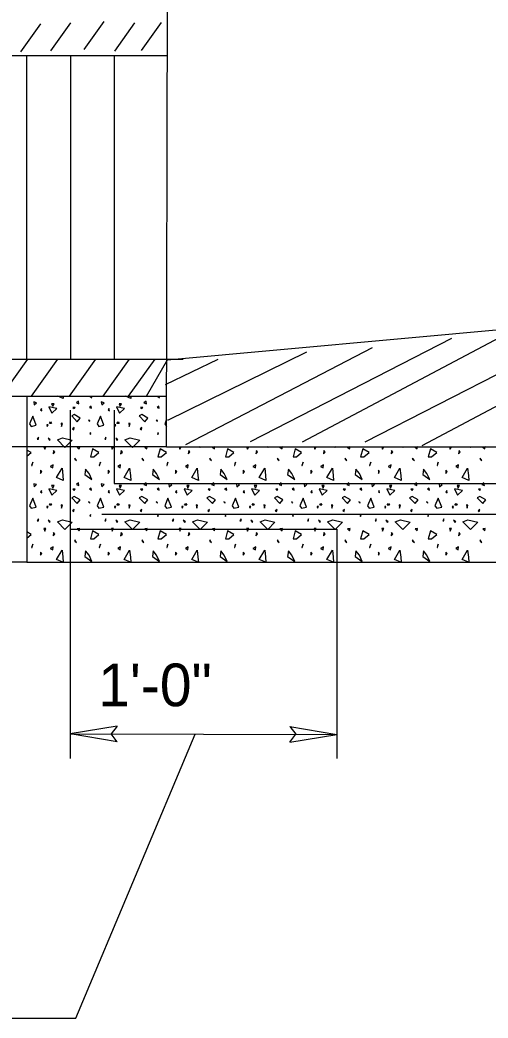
# Model space of a CAD drawing. Extents: x 9.6 to 16.8, y 2.2 to 12.2.
# Drawn here: x 11.1 to 11.758, y 6.233 to 7.637 of the extents above; entities that cross this region are included whole.
import ezdxf

# ---------------------------------------------------------------- set-up
doc = ezdxf.new("R2010")
doc.units = 0
for name, color, linetype in [('DETL-DIMS', 7, 'Continuous'), ('DETL-LINE', 7, 'Continuous'), ('DETL-NOTE', 7, 'Continuous'), ('DETL-PATT', 7, 'Continuous')]:
    doc.layers.add(name, color=color, linetype=linetype)

msp = doc.modelspace()

# ---------------------------------------------------------------- linework, layer by layer
at = {"layer": 'DETL-DIMS'}
for p, q in [((11.3059, 7.0371), (10.6784, 7.0371)), ((11.1705, 6.9211), (11.1705, 6.5984)), ((11.5452, 6.9211), (11.5452, 6.5984)), ((11.1096, 6.8747), (9.7269, 6.8747)), ((11.2365, 6.6441), (11.1705, 6.6332)), ((11.2365, 6.6441), (11.2282, 6.6331)), ((11.4794, 6.6436), (11.5452, 6.6325)), ((11.4794, 6.6436), (11.4876, 6.6326)), ((11.2364, 6.6221), (11.1705, 6.6332)), ((11.1705, 6.6332), (11.5452, 6.6325)), ((11.1787, 6.2335), (11.3462, 6.6329)), ((11.2364, 6.6221), (11.2282, 6.6331)), ((11.4793, 6.6216), (11.4876, 6.6326)), ((11.4793, 6.6216), (11.5452, 6.6325)), ((10.5653, 6.2335), (11.1787, 6.2335))]:
    msp.add_line(p, q, dxfattribs=at)
at = {"layer": 'DETL-LINE'}
for p, q in [((11.3059, 7.0371), (11.309, 8.5978)), ((10.8078, 7.5875), (11.3075, 7.5875)), ((11.1096, 7.1604), (11.1096, 7.5875)), ((11.1713, 7.1604), (11.1713, 7.5875)), ((11.2329, 7.1604), (11.2329, 7.5875)), ((11.3067, 7.1594), (13.2439, 7.3362)), ((10.8178, 7.1604), (11.3296, 7.1604)), ((10.7993, 7.1082), (11.3061, 7.1082)), ((11.1096, 7.1082), (11.1096, 6.8747)), ((11.1705, 7.0886), (11.1705, 6.9211)), ((11.2322, 7.0886), (11.2322, 6.9855)), ((11.3059, 7.0371), (13.2464, 7.0371)), ((11.2322, 6.9855), (13.2936, 6.9855)), ((11.2152, 6.9422), (13.3509, 6.9422)), ((11.1705, 6.9211), (11.5452, 6.9211)), ((11.1096, 6.8747), (13.4172, 6.8747))]:
    msp.add_line(p, q, dxfattribs=at)
at = {"layer": 'DETL-PATT'}
for p, q in [((11.1011, 7.5926), (11.1293, 7.6321)), ((11.1433, 7.5939), (11.1715, 7.6334)), ((11.1902, 7.5957), (11.2184, 7.6352)), ((11.2333, 7.5938), (11.2615, 7.6333)), ((11.2708, 7.5946), (11.299, 7.6341)), ((11.9041, 7.2071), (11.5849, 7.0436)), ((11.6655, 7.0387), (11.9979, 7.2154)), ((11.7067, 7.1896), (11.4236, 7.0439)), ((11.4972, 7.0442), (11.7831, 7.1956)), ((11.3331, 7.0403), (11.5955, 7.1767)), ((11.5027, 7.1703), (11.3074, 7.0742)), ((11.0738, 7.1082), (11.1112, 7.1604)), ((11.116, 7.1082), (11.1533, 7.1604)), ((11.1695, 7.1082), (11.2068, 7.1604)), ((11.2168, 7.1082), (11.2541, 7.1604)), ((11.2527, 7.1082), (11.29, 7.1604)), ((11.2776, 7.1082), (11.3076, 7.1604)), ((11.3047, 7.1246), (11.3784, 7.1602))]:
    msp.add_line(p, q, dxfattribs=at)
for points in [[(11.1605, 7.1082), (11.1608, 7.1049), (11.1533, 7.1082)], [(11.1982, 7.1082), (11.2012, 7.106), (11.2002, 7.1082)], [(11.2556, 7.1082), (11.2558, 7.1049), (11.2483, 7.1082)], [(11.2933, 7.1082), (11.2962, 7.106), (11.2952, 7.1082)], [(11.306, 7.0753), (11.3034, 7.0693), (11.3058, 7.0656), (11.306, 7.0657)], [(11.3236, 7.0371), (11.3247, 7.0336), (11.3265, 7.0371)], [(11.3543, 7.0371), (11.3532, 7.036), (11.3521, 7.0371)], [(11.3737, 7.0371), (11.3704, 7.0366), (11.3734, 7.0342), (11.374, 7.0371)], [(11.4186, 7.0371), (11.4197, 7.0336), (11.4215, 7.0371)], [(11.4493, 7.0371), (11.4482, 7.036), (11.4471, 7.0371)], [(11.4687, 7.0371), (11.4655, 7.0366), (11.4684, 7.0342), (11.469, 7.0371)], [(11.5136, 7.0371), (11.5147, 7.0336), (11.5165, 7.0371)], [(11.5444, 7.0371), (11.5433, 7.036), (11.5422, 7.0371)], [(11.5638, 7.0371), (11.5605, 7.0366), (11.5634, 7.0342), (11.564, 7.0371)], [(11.6086, 7.0371), (11.6097, 7.0336), (11.6115, 7.0371)], [(11.6393, 7.0371), (11.6382, 7.036), (11.6371, 7.0371)], [(11.6588, 7.0371), (11.6555, 7.0366), (11.6584, 7.0342), (11.659, 7.0371)], [(11.7036, 7.0371), (11.7047, 7.0336), (11.7065, 7.0371)], [(11.7344, 7.0371), (11.7333, 7.036), (11.7322, 7.0371)], [(11.7538, 7.0371), (11.7505, 7.0366), (11.7535, 7.0342), (11.754, 7.0371)], [(11.1096, 7.0238), (11.1158, 7.0289), (11.1096, 7.0325)], [(11.1096, 6.9086), (11.1158, 6.9138), (11.1096, 6.9173)], [(11.1604, 6.8747), (11.1513, 6.8786), (11.1591, 6.8917), (11.1602, 6.8816), (11.1608, 6.8747)], [(11.2555, 6.8747), (11.2464, 6.8786), (11.2541, 6.8917), (11.2553, 6.8816), (11.2558, 6.8747)], [(11.3505, 6.8747), (11.3414, 6.8786), (11.3491, 6.8917), (11.3502, 6.8816), (11.3508, 6.8747)], [(11.4455, 6.8747), (11.4364, 6.8786), (11.4441, 6.8917), (11.4453, 6.8816), (11.4458, 6.8747)], [(11.5405, 6.8747), (11.5314, 6.8786), (11.5391, 6.8917), (11.5403, 6.8816), (11.5408, 6.8747)], [(11.6355, 6.8747), (11.6264, 6.8786), (11.6342, 6.8917), (11.6353, 6.8816), (11.6358, 6.8747)], [(11.7305, 6.8747), (11.7214, 6.8786), (11.7292, 6.8917), (11.7303, 6.8816), (11.7309, 6.8747)]]:
    msp.add_lwpolyline(points, dxfattribs=at)
for points in [[(11.1193, 7.1001), (11.1198, 7.096), (11.1234, 7.099)], [(11.1287, 7.0888), (11.1306, 7.0877), (11.13, 7.0907)], [(11.1406, 7.0931), (11.1448, 7.0842), (11.1519, 7.0907)], [(11.1443, 7.0977), (11.146, 7.0942), (11.1478, 7.0977)], [(11.1745, 7.0925), (11.1763, 7.0907), (11.1775, 7.0925)], [(11.1822, 7.1014), (11.1793, 7.099), (11.1828, 7.0977)], [(11.1976, 7.0925), (11.2006, 7.0912), (11.2, 7.0942)], [(11.2143, 7.1001), (11.2149, 7.096), (11.2184, 7.099)], [(11.2238, 7.0888), (11.2256, 7.0877), (11.225, 7.0907)], [(11.2356, 7.0931), (11.2398, 7.0842), (11.2469, 7.0907)], [(11.2393, 7.0977), (11.241, 7.0942), (11.2428, 7.0977)], [(11.2695, 7.0925), (11.2713, 7.0907), (11.2725, 7.0925)], [(11.2773, 7.1014), (11.2743, 7.099), (11.2778, 7.0977)], [(11.2927, 7.0925), (11.2956, 7.0912), (11.2951, 7.0942)], [(11.1158, 7.0656), (11.1228, 7.0675), (11.118, 7.0799), (11.1134, 7.0693)], [(11.1727, 7.0806), (11.1804, 7.0723), (11.1847, 7.0775), (11.1763, 7.0823)], [(11.2108, 7.0656), (11.2178, 7.0675), (11.213, 7.0799), (11.2084, 7.0693)], [(11.2676, 7.0806), (11.2754, 7.0723), (11.2796, 7.0775), (11.2713, 7.0823)], [(11.1376, 7.0681), (11.1382, 7.0656), (11.1395, 7.0681)], [(11.143, 7.0723), (11.1443, 7.0699), (11.1413, 7.0699)], [(11.1578, 7.0705), (11.1585, 7.0656), (11.1596, 7.0699)], [(11.1739, 7.0621), (11.1756, 7.061), (11.1763, 7.064)], [(11.1982, 7.074), (11.1965, 7.0745), (11.1982, 7.0729)], [(11.2327, 7.0681), (11.2332, 7.0656), (11.2345, 7.0681)], [(11.238, 7.0723), (11.2393, 7.0699), (11.2363, 7.0699)], [(11.2528, 7.0705), (11.2535, 7.0656), (11.2547, 7.0699)], [(11.2689, 7.0621), (11.2706, 7.061), (11.2713, 7.064)], [(11.2932, 7.074), (11.2915, 7.0745), (11.2932, 7.0729)], [(11.1258, 7.0508), (11.1241, 7.0479), (11.1258, 7.0479)], [(11.1413, 7.0462), (11.1424, 7.0467), (11.1395, 7.0491)], [(11.1596, 7.0497), (11.1734, 7.0462), (11.1632, 7.036), (11.1525, 7.0467)], [(11.1995, 7.0568), (11.1982, 7.0556), (11.1989, 7.0544)], [(11.2208, 7.0508), (11.2191, 7.0479), (11.2208, 7.0479)], [(11.2363, 7.0462), (11.2375, 7.0467), (11.2345, 7.0491)], [(11.2547, 7.0497), (11.2684, 7.0462), (11.2582, 7.036), (11.2475, 7.0467)], [(11.2945, 7.0568), (11.2932, 7.0556), (11.2939, 7.0544)], [(11.1335, 7.0371), (11.1347, 7.0336), (11.1365, 7.0371)], [(11.1804, 7.0366), (11.1834, 7.0342), (11.184, 7.0371)], [(11.2036, 7.0229), (11.2108, 7.0289), (11.2019, 7.0342), (11.1989, 7.0229)], [(11.2285, 7.0371), (11.2297, 7.0336), (11.2315, 7.0371)], [(11.2754, 7.0366), (11.2784, 7.0342), (11.2789, 7.0371)], [(11.2986, 7.0229), (11.3058, 7.0289), (11.2969, 7.0342), (11.2939, 7.0229)], [(11.3936, 7.0229), (11.4008, 7.0289), (11.3919, 7.0342), (11.3889, 7.0229)], [(11.4886, 7.0229), (11.4958, 7.0289), (11.4869, 7.0342), (11.484, 7.0229)], [(11.5836, 7.0229), (11.5908, 7.0289), (11.5819, 7.0342), (11.5789, 7.0229)], [(11.6786, 7.0229), (11.6858, 7.0289), (11.6769, 7.0342), (11.674, 7.0229)], [(11.1473, 7.0319), (11.1465, 7.0271), (11.1489, 7.0295)], [(11.1769, 7.0212), (11.1769, 7.0194), (11.1793, 7.0176)], [(11.2422, 7.0319), (11.2415, 7.0271), (11.244, 7.0295)], [(11.2719, 7.0212), (11.2719, 7.0194), (11.2743, 7.0176)], [(11.3373, 7.0319), (11.3365, 7.0271), (11.3389, 7.0295)], [(11.3669, 7.0212), (11.3669, 7.0194), (11.3693, 7.0176)], [(11.4323, 7.0319), (11.4316, 7.0271), (11.434, 7.0295)], [(11.4619, 7.0212), (11.4619, 7.0194), (11.4643, 7.0176)], [(11.5273, 7.0319), (11.5266, 7.0271), (11.529, 7.0295)], [(11.5569, 7.0212), (11.5569, 7.0194), (11.5593, 7.0176)], [(11.6223, 7.0319), (11.6216, 7.0271), (11.624, 7.0295)], [(11.652, 7.0212), (11.652, 7.0194), (11.6544, 7.0176)], [(11.7173, 7.0319), (11.7166, 7.0271), (11.719, 7.0295)], [(11.7469, 7.0212), (11.7469, 7.0194), (11.7494, 7.0176)], [(11.1163, 7.0105), (11.1169, 7.0105), (11.118, 7.0153)], [(11.1424, 7.0093), (11.146, 7.0075), (11.1465, 7.0117)], [(11.1602, 6.9968), (11.1608, 6.9897), (11.1513, 6.9938), (11.1591, 7.0069)], [(11.2113, 7.0105), (11.2119, 7.0105), (11.213, 7.0153)], [(11.2375, 7.0093), (11.241, 7.0075), (11.2415, 7.0117)], [(11.2553, 6.9968), (11.2558, 6.9897), (11.2464, 6.9938), (11.2541, 7.0069)], [(11.3064, 7.0105), (11.3069, 7.0105), (11.308, 7.0153)], [(11.3325, 7.0093), (11.336, 7.0075), (11.3365, 7.0117)], [(11.3502, 6.9968), (11.3508, 6.9897), (11.3414, 6.9938), (11.3491, 7.0069)], [(11.4014, 7.0105), (11.4019, 7.0105), (11.4031, 7.0153)], [(11.4275, 7.0093), (11.431, 7.0075), (11.4316, 7.0117)], [(11.4453, 6.9968), (11.4458, 6.9897), (11.4364, 6.9938), (11.4441, 7.0069)], [(11.4964, 7.0105), (11.4969, 7.0105), (11.4981, 7.0153)], [(11.5225, 7.0093), (11.526, 7.0075), (11.5266, 7.0117)], [(11.5403, 6.9968), (11.5408, 6.9897), (11.5314, 6.9938), (11.5391, 7.0069)], [(11.5914, 7.0105), (11.592, 7.0105), (11.5931, 7.0153)], [(11.6175, 7.0093), (11.621, 7.0075), (11.6216, 7.0117)], [(11.6353, 6.9968), (11.6358, 6.9897), (11.6264, 6.9938), (11.6342, 7.0069)], [(11.6864, 7.0105), (11.6869, 7.0105), (11.6881, 7.0153)], [(11.7125, 7.0093), (11.716, 7.0075), (11.7166, 7.0117)], [(11.7303, 6.9968), (11.7309, 6.9897), (11.7214, 6.9938), (11.7292, 7.0069)], [(11.1287, 7.004), (11.1287, 6.9997), (11.1306, 7.0021)], [(11.1923, 7.0056), (11.1911, 6.998), (11.2012, 6.9908), (11.1971, 6.9997)], [(11.2238, 7.004), (11.2238, 6.9997), (11.2256, 7.0021)], [(11.2873, 7.0056), (11.2862, 6.998), (11.2962, 6.9908), (11.2921, 6.9997)], [(11.3188, 7.004), (11.3188, 6.9997), (11.3206, 7.0021)], [(11.3823, 7.0056), (11.3812, 6.998), (11.3912, 6.9908), (11.3871, 6.9997)], [(11.4138, 7.004), (11.4138, 6.9997), (11.4156, 7.0021)], [(11.4773, 7.0056), (11.4762, 6.998), (11.4862, 6.9908), (11.4821, 6.9997)], [(11.5088, 7.004), (11.5088, 6.9997), (11.5106, 7.0021)], [(11.5723, 7.0056), (11.5712, 6.998), (11.5812, 6.9908), (11.5771, 6.9997)], [(11.6038, 7.004), (11.6038, 6.9997), (11.6056, 7.0021)], [(11.6673, 7.0056), (11.6662, 6.998), (11.6762, 6.9908), (11.6721, 6.9997)], [(11.6988, 7.004), (11.6988, 6.9997), (11.7007, 7.0021)], [(11.1193, 6.9849), (11.1198, 6.9808), (11.1234, 6.9838)], [(11.1443, 6.9825), (11.146, 6.979), (11.1478, 6.9825)], [(11.1822, 6.9862), (11.1793, 6.9838), (11.1828, 6.9825)], [(11.1976, 6.9773), (11.2006, 6.976), (11.2, 6.979)], [(11.2143, 6.9849), (11.2149, 6.9808), (11.2184, 6.9838)], [(11.2393, 6.9825), (11.241, 6.979), (11.2428, 6.9825)], [(11.2773, 6.9862), (11.2743, 6.9838), (11.2778, 6.9825)], [(11.2927, 6.9773), (11.2956, 6.976), (11.2951, 6.979)], [(11.3093, 6.9849), (11.3099, 6.9808), (11.3134, 6.9838)], [(11.3343, 6.9825), (11.336, 6.979), (11.3378, 6.9825)], [(11.3723, 6.9862), (11.3693, 6.9838), (11.3728, 6.9825)], [(11.3876, 6.9773), (11.3906, 6.976), (11.3901, 6.979)], [(11.4043, 6.9849), (11.4049, 6.9808), (11.4084, 6.9838)], [(11.4293, 6.9825), (11.431, 6.979), (11.4328, 6.9825)], [(11.4673, 6.9862), (11.4643, 6.9838), (11.4678, 6.9825)], [(11.4827, 6.9773), (11.4856, 6.976), (11.4851, 6.979)], [(11.4993, 6.9849), (11.4999, 6.9808), (11.5034, 6.9838)], [(11.5243, 6.9825), (11.526, 6.979), (11.5278, 6.9825)], [(11.5623, 6.9862), (11.5593, 6.9838), (11.5629, 6.9825)], [(11.5777, 6.9773), (11.5807, 6.976), (11.5801, 6.979)], [(11.5944, 6.9849), (11.5949, 6.9808), (11.5984, 6.9838)], [(11.6193, 6.9825), (11.621, 6.979), (11.6229, 6.9825)], [(11.6573, 6.9862), (11.6544, 6.9838), (11.6579, 6.9825)], [(11.6727, 6.9773), (11.6756, 6.976), (11.6751, 6.979)], [(11.6894, 6.9849), (11.6899, 6.9808), (11.6935, 6.9838)], [(11.7144, 6.9825), (11.716, 6.979), (11.7179, 6.9825)], [(11.7523, 6.9862), (11.7494, 6.9838), (11.7529, 6.9825)], [(11.1158, 6.9505), (11.1228, 6.9523), (11.118, 6.9647), (11.1134, 6.9541)], [(11.1287, 6.9736), (11.1306, 6.9725), (11.13, 6.9755)], [(11.1406, 6.9778), (11.1448, 6.9689), (11.1519, 6.9755)], [(11.1727, 6.9654), (11.1804, 6.9571), (11.1847, 6.9623), (11.1763, 6.9671)], [(11.1745, 6.9773), (11.1763, 6.9755), (11.1775, 6.9773)], [(11.2108, 6.9505), (11.2178, 6.9523), (11.213, 6.9647), (11.2084, 6.9541)], [(11.2238, 6.9736), (11.2256, 6.9725), (11.225, 6.9755)], [(11.2356, 6.9778), (11.2398, 6.9689), (11.2469, 6.9755)], [(11.2676, 6.9654), (11.2754, 6.9571), (11.2796, 6.9623), (11.2713, 6.9671)], [(11.2695, 6.9773), (11.2713, 6.9755), (11.2725, 6.9773)], [(11.3058, 6.9505), (11.3128, 6.9523), (11.308, 6.9647), (11.3034, 6.9541)], [(11.3188, 6.9736), (11.3206, 6.9725), (11.32, 6.9755)], [(11.3306, 6.9778), (11.3349, 6.9689), (11.3419, 6.9755)], [(11.3627, 6.9654), (11.3704, 6.9571), (11.3747, 6.9623), (11.3664, 6.9671)], [(11.3645, 6.9773), (11.3664, 6.9755), (11.3675, 6.9773)], [(11.4008, 6.9505), (11.4078, 6.9523), (11.4031, 6.9647), (11.3984, 6.9541)], [(11.4138, 6.9736), (11.4156, 6.9725), (11.4151, 6.9755)], [(11.4256, 6.9778), (11.4299, 6.9689), (11.4369, 6.9755)], [(11.4577, 6.9654), (11.4655, 6.9571), (11.4697, 6.9623), (11.4614, 6.9671)], [(11.4595, 6.9773), (11.4614, 6.9755), (11.4625, 6.9773)], [(11.4958, 6.9505), (11.5029, 6.9523), (11.4981, 6.9647), (11.4934, 6.9541)], [(11.5088, 6.9736), (11.5106, 6.9725), (11.5101, 6.9755)], [(11.5207, 6.9778), (11.5249, 6.9689), (11.532, 6.9755)], [(11.5527, 6.9654), (11.5605, 6.9571), (11.5647, 6.9623), (11.5564, 6.9671)], [(11.5545, 6.9773), (11.5564, 6.9755), (11.5575, 6.9773)], [(11.5908, 6.9505), (11.5979, 6.9523), (11.5931, 6.9647), (11.5884, 6.9541)], [(11.6038, 6.9736), (11.6056, 6.9725), (11.6051, 6.9755)], [(11.6156, 6.9778), (11.6199, 6.9689), (11.6269, 6.9755)], [(11.6477, 6.9654), (11.6555, 6.9571), (11.6597, 6.9623), (11.6514, 6.9671)], [(11.6495, 6.9773), (11.6514, 6.9755), (11.6525, 6.9773)], [(11.6858, 6.9505), (11.6929, 6.9523), (11.6881, 6.9647), (11.6834, 6.9541)], [(11.6988, 6.9736), (11.7007, 6.9725), (11.7001, 6.9755)], [(11.7107, 6.9778), (11.7149, 6.9689), (11.722, 6.9755)], [(11.7427, 6.9654), (11.7505, 6.9571), (11.7547, 6.9623), (11.7464, 6.9671)], [(11.7445, 6.9773), (11.7464, 6.9755), (11.7475, 6.9773)], [(11.1376, 6.9529), (11.1382, 6.9505), (11.1395, 6.9529)], [(11.143, 6.9571), (11.1443, 6.9547), (11.1413, 6.9547)], [(11.1578, 6.9553), (11.1585, 6.9505), (11.1596, 6.9547)], [(11.1982, 6.9588), (11.1965, 6.9594), (11.1982, 6.9576)], [(11.2327, 6.9529), (11.2332, 6.9505), (11.2345, 6.9529)], [(11.238, 6.9571), (11.2393, 6.9547), (11.2363, 6.9547)], [(11.2528, 6.9553), (11.2535, 6.9505), (11.2547, 6.9547)], [(11.2932, 6.9588), (11.2915, 6.9594), (11.2932, 6.9576)], [(11.3276, 6.9529), (11.3282, 6.9505), (11.3295, 6.9529)], [(11.333, 6.9571), (11.3343, 6.9547), (11.3313, 6.9547)], [(11.3478, 6.9553), (11.3485, 6.9505), (11.3497, 6.9547)], [(11.3882, 6.9588), (11.3865, 6.9594), (11.3882, 6.9576)], [(11.4227, 6.9529), (11.4233, 6.9505), (11.4245, 6.9529)], [(11.428, 6.9571), (11.4293, 6.9547), (11.4264, 6.9547)], [(11.4429, 6.9553), (11.4436, 6.9505), (11.4447, 6.9547)], [(11.4833, 6.9588), (11.4815, 6.9594), (11.4833, 6.9576)], [(11.5177, 6.9529), (11.5182, 6.9505), (11.5195, 6.9529)], [(11.5231, 6.9571), (11.5243, 6.9547), (11.5214, 6.9547)], [(11.5379, 6.9553), (11.5386, 6.9505), (11.5397, 6.9547)], [(11.5782, 6.9588), (11.5765, 6.9594), (11.5782, 6.9576)], [(11.6127, 6.9529), (11.6133, 6.9505), (11.6145, 6.9529)], [(11.6181, 6.9571), (11.6193, 6.9547), (11.6164, 6.9547)], [(11.6329, 6.9553), (11.6336, 6.9505), (11.6347, 6.9547)], [(11.6733, 6.9588), (11.6716, 6.9594), (11.6733, 6.9576)], [(11.7077, 6.9529), (11.7083, 6.9505), (11.7095, 6.9529)], [(11.7131, 6.9571), (11.7144, 6.9547), (11.7114, 6.9547)], [(11.7279, 6.9553), (11.7286, 6.9505), (11.7297, 6.9547)], [(11.1739, 6.9469), (11.1756, 6.9458), (11.1763, 6.9488)], [(11.1995, 6.9416), (11.1982, 6.9404), (11.1989, 6.9392)], [(11.2689, 6.9469), (11.2706, 6.9458), (11.2713, 6.9488)], [(11.2945, 6.9416), (11.2932, 6.9404), (11.2939, 6.9392)], [(11.364, 6.9469), (11.3656, 6.9458), (11.3664, 6.9488)], [(11.3895, 6.9416), (11.3882, 6.9404), (11.3889, 6.9392)], [(11.4589, 6.9469), (11.4607, 6.9458), (11.4614, 6.9488)], [(11.4845, 6.9416), (11.4833, 6.9404), (11.484, 6.9392)], [(11.554, 6.9469), (11.5556, 6.9458), (11.5564, 6.9488)], [(11.5795, 6.9416), (11.5782, 6.9404), (11.5789, 6.9392)], [(11.649, 6.9469), (11.6507, 6.9458), (11.6514, 6.9488)], [(11.6745, 6.9416), (11.6733, 6.9404), (11.674, 6.9392)], [(11.744, 6.9469), (11.7457, 6.9458), (11.7464, 6.9488)], [(11.1258, 6.9356), (11.1241, 6.9327), (11.1258, 6.9327)], [(11.1335, 6.922), (11.1347, 6.9184), (11.1365, 6.922)], [(11.1413, 6.931), (11.1424, 6.9315), (11.1395, 6.934)], [(11.1596, 6.9345), (11.1734, 6.931), (11.1632, 6.9208), (11.1525, 6.9315)], [(11.1804, 6.9214), (11.1834, 6.919), (11.184, 6.922)], [(11.2208, 6.9356), (11.2191, 6.9327), (11.2208, 6.9327)], [(11.2285, 6.922), (11.2297, 6.9184), (11.2315, 6.922)], [(11.2363, 6.931), (11.2375, 6.9315), (11.2345, 6.934)], [(11.2547, 6.9345), (11.2684, 6.931), (11.2582, 6.9208), (11.2475, 6.9315)], [(11.2754, 6.9214), (11.2784, 6.919), (11.2789, 6.922)], [(11.3158, 6.9356), (11.3141, 6.9327), (11.3158, 6.9327)], [(11.3236, 6.922), (11.3247, 6.9184), (11.3265, 6.922)], [(11.3313, 6.931), (11.3325, 6.9315), (11.3295, 6.934)], [(11.3497, 6.9345), (11.3634, 6.931), (11.3532, 6.9208), (11.3425, 6.9315)], [(11.3704, 6.9214), (11.3734, 6.919), (11.374, 6.922)], [(11.4108, 6.9356), (11.4091, 6.9327), (11.4108, 6.9327)], [(11.4186, 6.922), (11.4197, 6.9184), (11.4215, 6.922)], [(11.4264, 6.931), (11.4275, 6.9315), (11.4245, 6.934)], [(11.4447, 6.9345), (11.4584, 6.931), (11.4482, 6.9208), (11.4375, 6.9315)], [(11.4655, 6.9214), (11.4684, 6.919), (11.469, 6.922)], [(11.5058, 6.9356), (11.5041, 6.9327), (11.5058, 6.9327)], [(11.5136, 6.922), (11.5147, 6.9184), (11.5165, 6.922)], [(11.5214, 6.931), (11.5225, 6.9315), (11.5195, 6.934)], [(11.5397, 6.9345), (11.5534, 6.931), (11.5433, 6.9208), (11.5325, 6.9315)], [(11.5605, 6.9214), (11.5634, 6.919), (11.564, 6.922)], [(11.6008, 6.9356), (11.5991, 6.9327), (11.6008, 6.9327)], [(11.6086, 6.922), (11.6097, 6.9184), (11.6116, 6.922)], [(11.6164, 6.931), (11.6175, 6.9315), (11.6145, 6.934)], [(11.6347, 6.9345), (11.6484, 6.931), (11.6382, 6.9208), (11.6275, 6.9315)], [(11.6555, 6.9214), (11.6584, 6.919), (11.659, 6.922)], [(11.6958, 6.9356), (11.6942, 6.9327), (11.6958, 6.9327)], [(11.7036, 6.922), (11.7047, 6.9184), (11.7066, 6.922)], [(11.7114, 6.931), (11.7125, 6.9315), (11.7095, 6.934)], [(11.7297, 6.9345), (11.7434, 6.931), (11.7333, 6.9208), (11.7225, 6.9315)], [(11.7505, 6.9214), (11.7535, 6.919), (11.754, 6.922)], [(11.1473, 6.9167), (11.1465, 6.9119), (11.1489, 6.9143)], [(11.2036, 6.9077), (11.2108, 6.9138), (11.2019, 6.919), (11.1989, 6.9077)], [(11.2422, 6.9167), (11.2415, 6.9119), (11.244, 6.9143)], [(11.2986, 6.9077), (11.3058, 6.9138), (11.2969, 6.919), (11.2939, 6.9077)], [(11.3373, 6.9167), (11.3365, 6.9119), (11.3389, 6.9143)], [(11.3936, 6.9077), (11.4008, 6.9138), (11.3919, 6.919), (11.3889, 6.9077)], [(11.4323, 6.9167), (11.4316, 6.9119), (11.434, 6.9143)], [(11.4886, 6.9077), (11.4958, 6.9138), (11.4869, 6.919), (11.484, 6.9077)], [(11.5273, 6.9167), (11.5266, 6.9119), (11.529, 6.9143)], [(11.5836, 6.9077), (11.5908, 6.9138), (11.5819, 6.919), (11.5789, 6.9077)], [(11.6223, 6.9167), (11.6216, 6.9119), (11.624, 6.9143)], [(11.6786, 6.9077), (11.6858, 6.9138), (11.6769, 6.919), (11.674, 6.9077)], [(11.7173, 6.9167), (11.7166, 6.9119), (11.719, 6.9143)], [(11.1163, 6.8953), (11.1169, 6.8953), (11.118, 6.9001)], [(11.1424, 6.8941), (11.146, 6.8923), (11.1465, 6.8965)], [(11.1769, 6.906), (11.1769, 6.9042), (11.1793, 6.9025)], [(11.2113, 6.8953), (11.2119, 6.8953), (11.213, 6.9001)], [(11.2375, 6.8941), (11.241, 6.8923), (11.2415, 6.8965)], [(11.2719, 6.906), (11.2719, 6.9042), (11.2743, 6.9025)], [(11.3064, 6.8953), (11.3069, 6.8953), (11.308, 6.9001)], [(11.3325, 6.8941), (11.336, 6.8923), (11.3365, 6.8965)], [(11.3669, 6.906), (11.3669, 6.9042), (11.3693, 6.9025)], [(11.4014, 6.8953), (11.4019, 6.8953), (11.4031, 6.9001)], [(11.4275, 6.8941), (11.431, 6.8923), (11.4316, 6.8965)], [(11.4619, 6.906), (11.4619, 6.9042), (11.4643, 6.9025)], [(11.4964, 6.8953), (11.4969, 6.8953), (11.4981, 6.9001)], [(11.5225, 6.8941), (11.526, 6.8923), (11.5266, 6.8965)], [(11.5569, 6.906), (11.5569, 6.9042), (11.5593, 6.9025)], [(11.5914, 6.8953), (11.592, 6.8953), (11.5931, 6.9001)], [(11.6175, 6.8941), (11.621, 6.8923), (11.6216, 6.8965)], [(11.652, 6.906), (11.652, 6.9042), (11.6544, 6.9025)], [(11.6864, 6.8953), (11.6869, 6.8953), (11.6881, 6.9001)], [(11.7125, 6.8941), (11.716, 6.8923), (11.7166, 6.8965)], [(11.7469, 6.906), (11.7469, 6.9042), (11.7494, 6.9025)], [(11.1287, 6.8888), (11.1287, 6.8845), (11.1306, 6.8869)], [(11.1923, 6.8905), (11.1911, 6.8828), (11.2012, 6.8756), (11.1971, 6.8845)], [(11.2238, 6.8888), (11.2238, 6.8845), (11.2256, 6.8869)], [(11.2873, 6.8905), (11.2862, 6.8828), (11.2962, 6.8756), (11.2921, 6.8845)], [(11.3188, 6.8888), (11.3188, 6.8845), (11.3206, 6.8869)], [(11.3823, 6.8905), (11.3812, 6.8828), (11.3912, 6.8756), (11.3871, 6.8845)], [(11.4138, 6.8888), (11.4138, 6.8845), (11.4156, 6.8869)], [(11.4773, 6.8905), (11.4762, 6.8828), (11.4862, 6.8756), (11.4821, 6.8845)], [(11.5088, 6.8888), (11.5088, 6.8845), (11.5106, 6.8869)], [(11.5723, 6.8905), (11.5712, 6.8828), (11.5812, 6.8756), (11.5771, 6.8845)], [(11.6038, 6.8888), (11.6038, 6.8845), (11.6056, 6.8869)], [(11.6673, 6.8905), (11.6662, 6.8828), (11.6762, 6.8756), (11.6721, 6.8845)], [(11.6988, 6.8888), (11.6988, 6.8845), (11.7007, 6.8869)]]:
    msp.add_lwpolyline(points, close=True, dxfattribs=at)

# ---------------------------------------------------------------- texts
at = {"layer": 'DETL-NOTE'}
msp.add_text('1\'-0"', height=0.06, dxfattribs=at).set_placement((11.2099, 6.6721))

doc.saveas('drawing.dxf')
